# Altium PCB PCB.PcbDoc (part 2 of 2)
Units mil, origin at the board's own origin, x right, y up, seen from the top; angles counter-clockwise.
Board outline 2750 x 2500 mil, 2 copper layers (Top Layer, Bottom Layer), stack 62 mil thick; 49 components, 22 nets, 97 pads, 5 vias.
Unrouted connection lines stored in the file: 2.
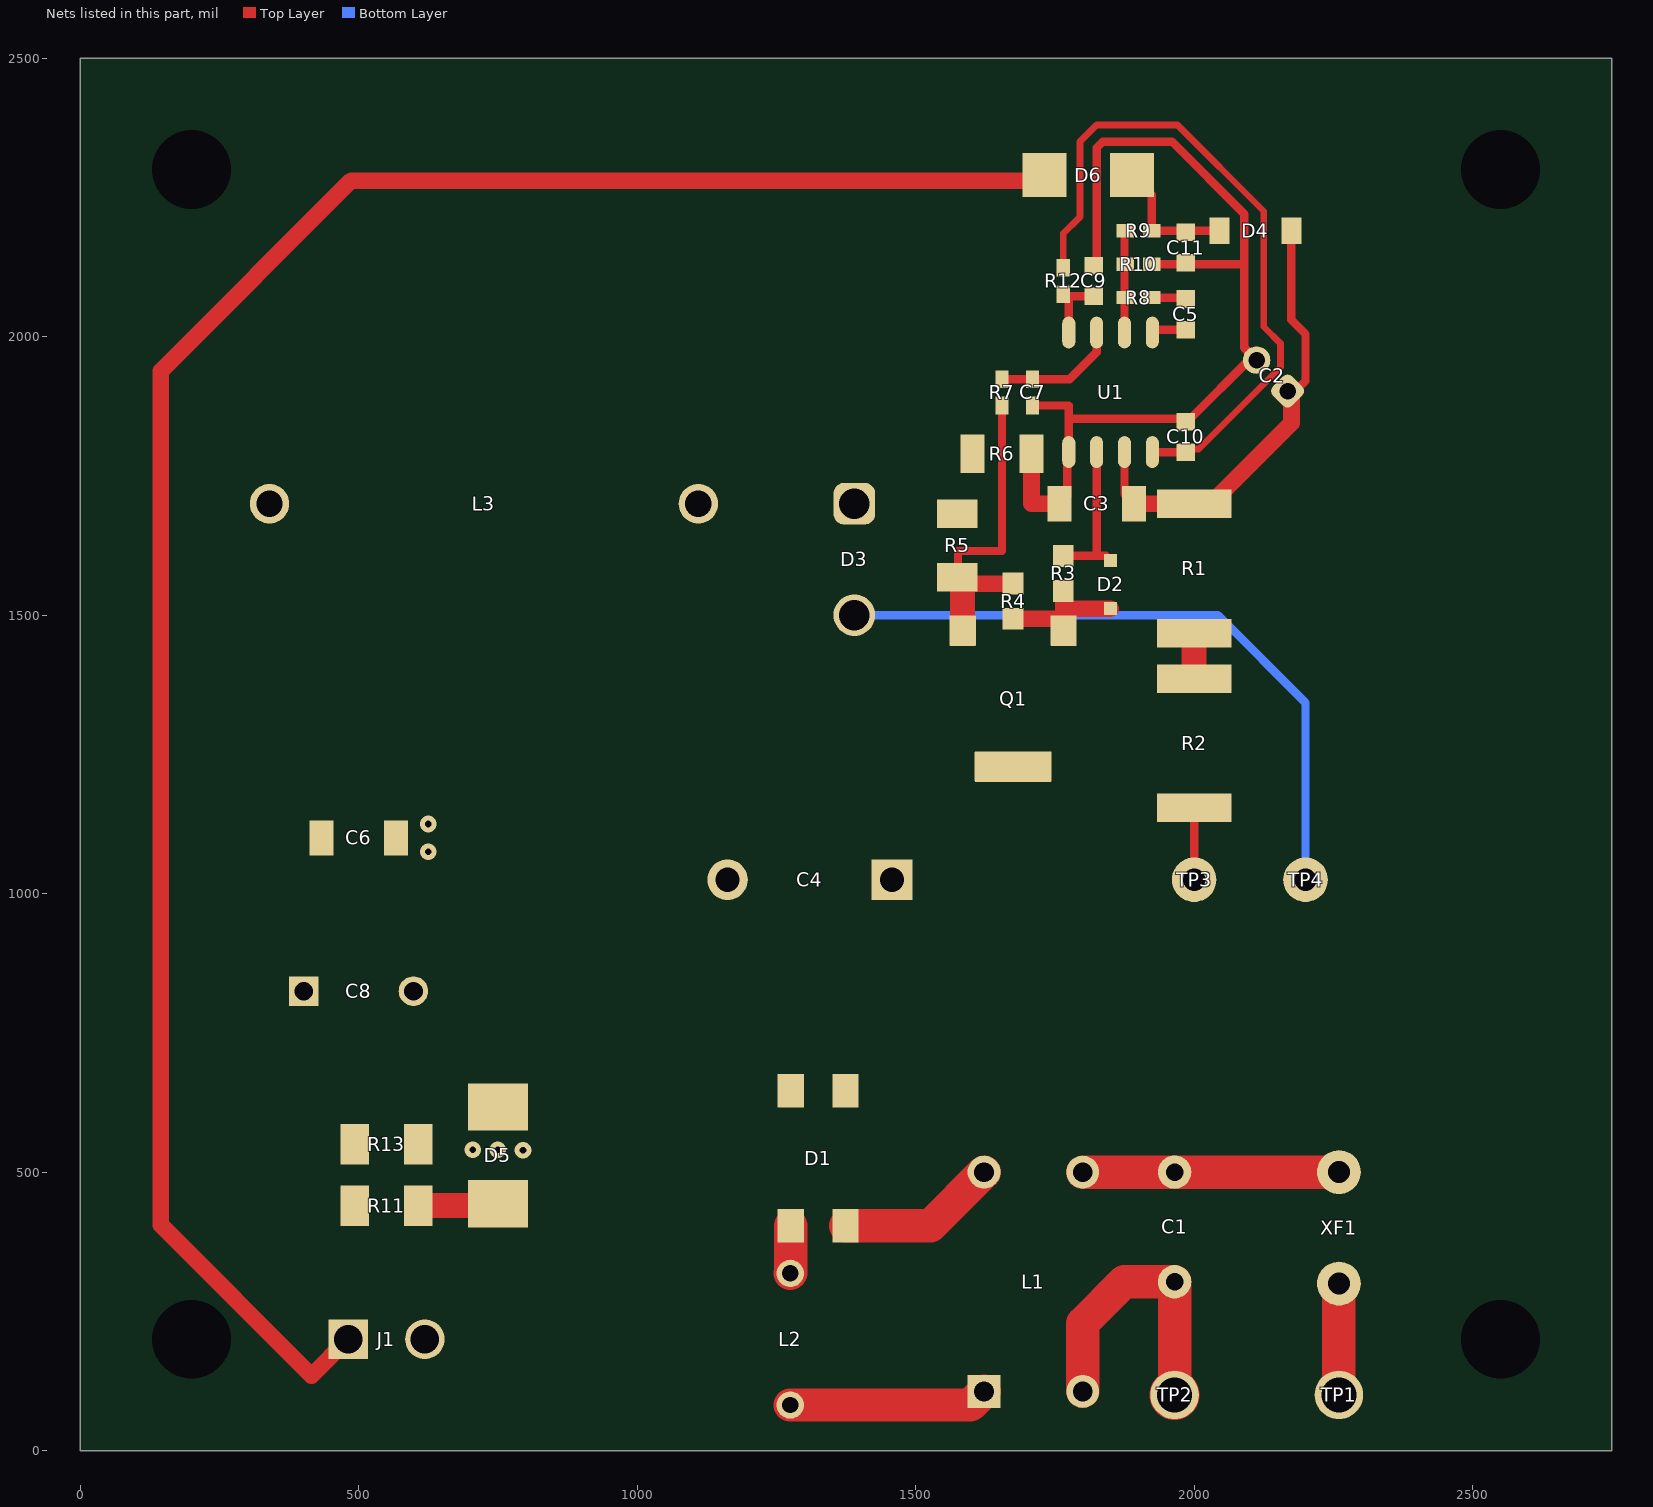
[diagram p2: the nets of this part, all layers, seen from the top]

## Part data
C1: library part CMP-0012332-3, "CAP, Film, 0.1 uF, 250 V, +/- 10%, TH", Cap_Case=4.5x9.5x7.3mm, Manufacturer=TDK, Supplier Part Number 1=495-2532-ND, Tolerance_%=10%, Value1=Unknown, Value2=250V, ValueDisplayed=0.1uF
C2: library part CMP-0064886-1, "CAP, AL, 22 uF, 25 V, +/- 20%, TH", Cap_Case=5x11mm, Manufacturer=Nichicon, Supplier Part Number 1=493-12773-1-ND, Tolerance_%=20%, Value1=Unknown, Value2=25V, ValueDisplayed=22uF
C3 C6: library part CMP-0008968-2, "CAP, CERM, 2.2 uF, 50 V, +/- 10%, X7R, 1206", Cap_Case=1206, Manufacturer=MuRata, Supplier Part Number 1=490-3367-1-ND, TempCo=X7R, Tolerance_%=10%, Value1=Unknown, Value2=50V, ValueDisplayed=2.2uF
C4: library part CMP-0010021-3, "CAP, AL, 47 uF, 250 V, +/- 20%, 0.380955 ohm, TH", AC_Derating=0.3, Manufacturer=Panasonic, Supplier Part Number 1=P13536-ND, Tolerance_%=20%, Value1="0.380955 ohm", Value2=250V, ValueDisplayed=47uF
C5 C11: library part CMP-0007415-4, "CAP, CERM, 0.22 uF, 25 V, +/- 10%, X7R, 0603", Cap_Case=0603, Manufacturer=MuRata, Supplier Part Number 1=490-3290-1-ND, TempCo=X7R, Tolerance_%=10%, Value1=Unknown, Value2=25V, ValueDisplayed=0.22uF
C7: library part CMP-0006410-2, "CAP, CERM, 100 pF, 50 V, +/- 5%, C0G/NP0, 0402", Cap_Case=0402, Manufacturer=MuRata, Supplier Part Number 1=81-GRM1555C1H101JA1D, TempCo=C0G/NP0, Tolerance_%=5%, Value1=Unknown, Value2=50V, ValueDisplayed=100pF
C8: library part CMP-0010541-2, "CAP, AL, 470 uF, 35 V, +/- 20%, 0.03 ohm, TH", Cap_Case=10x16mm, Manufacturer=Nichicon, Supplier Part Number 1=493-6882-ND, Tolerance_%=20%, Value1="0.03 ohm", Value2=35V, ValueDisplayed=470uF
C9: library part CMP-0007402-5, "CAP, CERM, 1000 pF, 25 V, +/- 10%, X7R, 0603", Cap_Case=0603, Manufacturer=MuRata, Supplier Part Number 1=GRM188R71E102KA01D-ND, TempCo=X7R, Tolerance_%=10%, Value1=Unknown, Value2=25V, ValueDisplayed=1000pF
C10: library part CMP-0007405-5, "CAP, CERM, 1 uF, 25 V, +/- 10%, X7R, 0603", Cap_Case=0603, Manufacturer=MuRata, Supplier Part Number 1=490-5307-1-ND, TempCo=X7R, Tolerance_%=10%, Value1=Unknown, Value2=25V, ValueDisplayed=1uF
D1: library part CMP-0029217-3, "Diode, Switching-Bridge, 400 V, 0.8 A, MiniDIP", Manufacturer="Diodes Inc.", Value1=0.8A, Value2=1V
D2: library part CMP-0029045-2, "Diode, Switching, 100 V, 0.2 A, SOD-323", Manufacturer="Micro Commercial Components", Value1=0.2A, Value2=1V
D3: library part CMP-0028844-2, "Diode, Schottky, 300 V, 30 A, TH", Manufacturer="Power Integrations", Value1=30A, Value2=1.95V
D4: library part CMP-0029001-2, "Diode, Ultrafast, 100 V, 0.15 A, SOD-123", Manufacturer="Diodes Inc.", Value1=0.15A, Value2=1.25V
D5: library part CMP-0005557-4, "Diode, TVS, Uni, 24 V, 38.9 Vc, SMB", Manufacturer="Diodes Inc.", Value1=600W
D6: library part CMP-0067545-2, "Diode, Superfast Rectifier, 600 V, 1 A, SMA", Manufacturer="SMC Diode Solutions", Value1=1A, Value2=1.7V
H1 H2 H3 H4: library part CMP-0003652-1, Manufacturer=Keystone, Supplier Part Number 1=36-4820-ND
J1: library part CMP-0054825-2, "Terminal Block, 3.5mm, 2x1, Tin, TH", Color=Green, Current_A=10A, Manufacturer="Wurth Elektronik", Supplier Part Number 1=732-2747-ND, Voltage_V=300V
L1: library part CMP-0084275-1, "Coupled inductor, 5 mH, 0.22 ohm, TH", Manufacturer="Wurth Elektronik", ValueDisplayed=5mH
L2: library part CMP-0064732-2, "Inductor, Toroid, Powdered Iron, 140 uH, 1 A, 0.11 ohm, TH", Manufacturer="Wurth Elektronik", Value1="0.11 ohm", Value2=1A, ValueDisplayed=140uH
L3: library part CMP-0074883-1, "Inductor, Wirewound, Ferrite, 470 µH, 4 A, 0.187 ohm, TH", Manufacturer=Bourns, Supplier Part Number 1=M8368-ND, Value1="0.187 ohm", Value2=4A, ValueDisplayed=470µH
LOGO1: library part CMP-0074835-1, "IEC 61010-1 High Voltage Warning"
Logo2: library part CMP-0074769-1
Logo3: library part CMP-0074847-1, "FCC_disclaimer"
Logo4: library part CMP-0074836-1, "IEC 61010-1 Caution Warning"
Q1: library part CMP-0087676-1, "MOSFET N-CHANNEL 600V 9A SOT223", Manufacturer=Infineon
R1 R2: library part CMP-0015941-3, "RES, 330 k, 5%, 1 W, AEC-Q200 Grade 0, 2512", Manufacturer=Vishay-Dale, PartNumber=CRCW2512330KJNEG, Power_W=1W, Supplier Part Number 1=541-330KXCT-ND, TempCo="200 ppm/C", Tolerance_%=5%, Value_Code=330k
R3: library part CMP-0022003-4, "RES, 10.0, 1%, 0.1 W, AEC-Q200 Grade 0, 0603", Manufacturer=Vishay-Dale, Power_W=100mW, Supplier Part Number 1=541-10.0HCT-ND, TempCo="100 ppm/C", Tolerance_%=1%, Value2=0.1W, Value_Code=10R0, ValueDisplayed=10.0
R4: library part CMP-0021990-4, "RES, 100 k, 1%, 0.1 W, AEC-Q200 Grade 0, 0603", Manufacturer=Vishay-Dale, Power_W=100mW, Supplier Part Number 1=541-100KHCT-ND, TempCo="100 ppm/C", Tolerance_%=1%, Value2=0.1W, Value_Code=100k
R5: library part CMP-0017274-2, "RES, 0.62, 1%, 0.5 W, 1206", Manufacturer="Stackpole Electronics Inc", Power_W=500mW, Supplier Part Number 1=CSR1206FTR620-ND, TempCo="100 ppm/C", Tolerance_%=1%, Value2=0.5W, Value_Code=R620, ValueDisplayed=0.62
R6: library part CMP-0018573-3, "RES, 0, 5%, 0.25 W, AEC-Q200 Grade 0, 1206", Manufacturer=Vishay-Dale, Power_W=250mW, Supplier Part Number 1=541-0.0ECT-ND, TempCo="200 ppm/C", Tolerance_%=5%, Value2=0.25W, Value_Code=0000, ValueDisplayed=0
R7: library part CMP-0026436-2, "RES, 511, 1%, 0.063 W, AEC-Q200 Grade 0, 0402", Manufacturer=Vishay-Dale, Power_W=63mW, Supplier Part Number 1=541-511LCT-ND, TempCo="100 ppm/C", Tolerance_%=1%, Value2=0.063W, Value_Code=511R, ValueDisplayed=511
R8: library part CMP-0026403-2, "RES, 49.9 k, 1%, 0.063 W, AEC-Q200 Grade 0, 0402", Manufacturer=Vishay-Dale, Power_W=63mW, Supplier Part Number 1=541-49.9KLCT-ND, TempCo="100 ppm/C", Tolerance_%=1%, Value2=0.063W, Value_Code=49k9, ValueDisplayed=49.9k
R9: library part CMP-0026178-2, "RES, 22.1 k, 1%, 0.063 W, AEC-Q200 Grade 0, 0402", Manufacturer=Vishay-Dale, Power_W=63mW, Supplier Part Number 1=541-22.1KLCT-ND, TempCo="100 ppm/C", Tolerance_%=1%, Value2=0.063W, Value_Code=22k1, ValueDisplayed=22.1k
R10: library part CMP-0026237-2, "RES, 2.49 k, 1%, 0.063 W, AEC-Q200 Grade 0, 0402", Manufacturer=Vishay-Dale, Power_W=63mW, Supplier Part Number 1=541-2.49KLCT-ND, TempCo="100 ppm/C", Tolerance_%=1%, Value2=0.063W, Value_Code=2k49, ValueDisplayed=2.49k
R11: library part CMP-0016583-3, "RES, 10.0, 1%, 0.25 W, AEC-Q200 Grade 0, 1206", Manufacturer=Vishay-Dale, PartNumber=CRCW120610R0FKEA, Power_W=250mW, Supplier Part Number 1=541-10.0FCT-ND, TempCo="100 ppm/C", Tolerance_%=1%, Value2=0.25W, Value_Code=10R0, ValueDisplayed=10.0
R12: library part CMP-0026371-2, "RES, 41.2 k, 1%, 0.063 W, AEC-Q200 Grade 0, 0402", Manufacturer=Vishay-Dale, Power_W=63mW, Supplier Part Number 1=541-41.2KLCT-ND, TempCo="100 ppm/C", Tolerance_%=1%, Value2=0.063W, Value_Code=41k2, ValueDisplayed=41.2k
R13: library part CMP-0018703-3, "RES, 5.1 k, 5%, 0.25 W, AEC-Q200 Grade 0, 1206", Manufacturer=Vishay-Dale, PartNumber=CRCW12065K10JNEA, Power_W=250mW, Supplier Part Number 1=541-5.1KECT-ND, TempCo="200 ppm/C", Tolerance_%=5%, Value2=0.25W, Value_Code=5k10, ValueDisplayed=5.1k
TP1: library part CMP-0055157-1, "Test Point, Multipurpose, Brown, TH", Color=Brown, Manufacturer=Keystone, Supplier Part Number 1=36-5125-ND
TP2: library part CMP-0055156-1, "Test Point, Multipurpose, Blue, TH", Color=Blue, Manufacturer=Keystone, Supplier Part Number 1=36-5127-ND
TP3: library part CMP-0055137-1, "Test Point, Miniature, Red, TH", Color=Red, Manufacturer=Keystone, Supplier Part Number 1=36-5000-ND
TP4: library part CMP-0055138-1, "Test Point, Miniature, Black, TH", Color=Black, Manufacturer=Keystone, Supplier Part Number 1=36-5001-ND
U1: library part CMP-0031461-1, "High-Performance Current-Mode PWM Controllers with Current control, 100% Duty Cycle, -40 to 85 degC, 8-pin SOIC (D),Green (RoHS & no Sb/Br)", Frequency(Max)(kHz)=500, Manufacturer="Texas Instruments", Rating=Catalog
XF1: library part CMP-0003627-1, "Fuse Holder, TR5, TH", Manufacturer=Littelfuse, Supplier Part Number 1=WK6235-ND

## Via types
v1: diameter 30, hole 12, Top Layer to Bottom Layer, 5 vias

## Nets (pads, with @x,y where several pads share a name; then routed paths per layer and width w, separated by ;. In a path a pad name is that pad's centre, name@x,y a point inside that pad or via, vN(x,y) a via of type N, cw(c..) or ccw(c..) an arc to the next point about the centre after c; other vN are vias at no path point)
24V: C6.1 C8.1 D6.2 J1.1 L3.2 R11.2 R13.2 | length 3740.6
  Top Layer w30: J1.1@481.1,200 415.55,134.45 145,405 145,1938.42 486.58,2280 1721.26,2280 D6.2@1731.26,2290
CS: Q1.3 R4.2 R5.1 R7.1 | length 578.2
  Top Layer w15: R5.1@1584.45,1558.46 1575.99,1566.91 1575.99,1615 1655,1615 R7.1@1655,1876.37
  Top Layer w30: R5.1@1584.45,1558.46 1586.41,1556.49 R4.2@1675,1556.49
  Top Layer w45: Q1.3@1584.45,1472.04 R5.1@1584.45,1558.46
GND: C4.2 C6.2 C8.2 D1.2 D3.3 D5.2 J1.2 R13.1 TP4.1 | length 1207.9
  Bottom Layer w15: D3.3@1375,1500 2042.7,1500 2200,1342.7 TP4.1@2200,1025
  other v1: 795,539.37 705,540 750,540 625,1075 625,1125
NetC1_1: C1.1 D1.4 L1.3 L1.4 XF1.2 | length 748.4
  Top Layer w60: D1.4@1374.21,403.93 1526.76,403.93 L1.4@1622.83,500 ; L1.3@1800,500 C1.1@1965,500 XF1.2@2260,500
NetC1_2: C1.2 L1.1 L1.2 L2.1 TP2.1 | length 879.4
  Top Layer w60: L2.1@1275,81.88 1598.42,81.88 L1.1@1622.83,106.3 ; L1.2@1800,106.3 1800,228.82 1874.33,303.15 C1.2@1965,303.15 TP2.1@1965,99.99
NetC2_2: C2.2 C3.2 C7.1 C9.2 C10.2 C11.2 R6.2 R10.1 U1.5 | length 1731.8
  Top Layer w15: C7.1@1710,1876.37 1775,1876.37 1775,1852.56 ; C3.2@1758.07,1700 1772.28,1714.21 1772.28,1790 U1.5@1775,1792.71 1775,1852.56 ; C9.2@1820,2127.56 1825,2132.56 1825,2338.89 1836.11,2350 1960,2350 2090,2220 2090,2130 ; R10.1@1923.62,2130 2090,2130 ; C10.2@1985,1847.56 1987.96,1847.56 2105.2,1964.8 2090,1980 2090,2130 ; C10.2@1985,1852.56 1775,1852.56
  Top Layer w30: R6.2@1708.15,1790 1708.15,1700 C3.2@1758.07,1700
NetC4_1: C4.1 D1.1 Q1.2 R2.1 TP3.1 | length 128.9
  Top Layer w15: TP3.1@2000,1025 R2.1@2000,1153.86
NetC5_1: C5.1 U1.1 | length 62.1
  Top Layer w15: U1.1@1925,2007.28 1930.15,2012.44 C5.1@1985,2012.44
NetC5_2: C5.2 R8.1 | length 62.4
  Top Layer w15: R8.1@1923.62,2070 1982.56,2070 C5.2@1985,2067.56
NetC7_2: C7.2 R7.2 U1.3 | length 225.4
  Top Layer w15: R7.2@1655,1923.62 C7.2@1710,1923.62 1776.72,1923.62 1825,1971.9 U1.3@1825,2007.28
NetC9_1: C9.1 R12.1 U1.4 | length 124.3
  Top Layer w15: R12.1@1765,2076.37 R12.1@1768.93,2072.44 ; U1.4@1775,2007.28 1775,2066.37 R12.1@1768.93,2072.44 ; C9.1@1820,2072.44 R12.1@1768.93,2072.44
NetC10_1: C10.1 R12.2 U1.8 | length 1231.2
  Top Layer w12: R12.2@1765,2123.62 1765,2185 1795,2215 1795,2350 1825,2380 1970,2380 2125,2225 2125,2017.82 2155,1987.82 2155,1945 2008.34,1798.35 C10.1@1990.91,1798.35
  Top Layer w15: U1.8@1925,1792.71 1984.73,1792.71 C10.1@1985,1792.44 C10.1@1990.91,1798.35
NetC11_1: C11.1 D4.2 D6.1 R9.2 | length 236.4
  Top Layer w15: D6.1@1888.74,2290 1923.62,2255.11 R9.2@1923.62,2190 D4.2@2045.53,2190
NetD1_3: D1.3 L2.2 | length 86.2
  Top Layer w60: L2.2@1275,318.1 1275.79,318.89 D1.3@1275.79,403.93
NetD2_1: D2.1 R3.2 U1.6 | length 274.6
  Top Layer w15: R3.2@1765,1606.49 1825,1606.49 ; U1.6@1825,1792.71 1825,1606.49 ; D2.1@1850,1598.3 1841.81,1606.49 1825,1606.49
NetD2_2: D2.2 Q1.1 R3.1 R4.1 | length 224.3
  Top Layer w30: R4.1@1675,1493.5 1763.5,1493.5 1765,1495 R3.1@1765,1543.5 ; 1765.55,1510 1767.24,1511.69 D2.2@1850,1511.69
NetD3_1: D3.1 L3.1 R5.2 R6.1
NetD5_1: D5.1 R11.1 | length 144.2
  Top Layer w45: R11.1@607.09,440 747.01,440 D5.1@750,442.99
NetR1_1: R1.1 R2.2 | length 81.6
  Top Layer w45: R2.2@2000,1386.14 R1.1@2000,1467.72
NetR8_2: R8.2 R9.1 R10.2 U1.2 | length 183.3
  Top Layer w15: U1.2@1875,2007.28 1875,2188.62 R9.1@1876.38,2190
NetTP1_1: TP1.1 XF1.1 | length 200
  Top Layer w60: TP1.1@2260,100 XF1.1@2260,300
VCC: C2.1 C3.1 D4.1 R1.2 U1.7 | length 808.8
  Top Layer w15: U1.7@1875,1792.71 1875,1716.93 C3.1@1891.93,1700 ; D4.1@2174.47,2190 2174.47,2030 2200,2004.47 2200,1920.4 C2.1@2174.8,1895.2
  Top Layer w30: C3.1@1891.93,1700 R1.2@2000,1700 2030,1700 2174.8,1844.8 C2.1@2174.8,1895.2
pads on no net: H1.0 H1.MH H2.0 H2.MH H3.0 H3.MH H4.0 H4.MH

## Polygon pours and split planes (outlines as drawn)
NetC2_2 on Top Layer "Top Layer-No Net 6" (solid, remove dead copper, pour order 10): 1745,1665 1745,2300 1825,2380 1975,2380 2150,2205 2150,1940 1875,1665
NetD3_1 on Top Layer "Top Layer-No Net 6" (solid, remove dead copper, pour order 8): 1625,1830 1625,1645 1115,1645 1085,1675 1085,1725 1190,1830
no net on Top Layer "Top Layer-No Net 6" (solid, remove dead copper, pour order 6): 1625,1828.39
GND on Top Layer "Top Layer-No Net 6" (solid, remove dead copper, pour order 4): 1300,615 1300,1050 1510,1260 1510,1440 1360,1590 500,1590 500,785 550,735 550,160 735,160 1190,615
NetC4_1 on Top Layer "Top Layer-No Net 6" (solid, remove dead copper, pour order 2): 1350,615 1350,1025 1600,1275 2070,1275 2070,1125 1910,1125 1400,615
24V on Top Layer "Top Layer-No Net 6" (solid, remove dead copper, pour order 0): 550,160 550,735 500,785 500,1590 365,1725 315,1725 180,1590 180,420 440,160
GND on Bottom Layer "Top Layer-No Net 6" (solid, remove dead copper, pour order 12): 0,0 0,2500 2750,2500 2750,1125 1910,1125 1400,615 1190,615 745,170 745,0

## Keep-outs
Keep-Out Layer:
  text ".Layer_Name" at 577,-858.49 h60

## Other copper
Top Layer:
  pour cut-out: 1925,1958.46 1840.63,1958.46 1840.63,2252.51
  pour cut-out: 1925,1841.53 1825,1841.53 1792.73,1809.27 1792.73,1656.84
  text ".Layer_Name" at 577,-858.49 h60
Bottom Layer:
  text ".Layer_Name" at 577,-858.49 h60

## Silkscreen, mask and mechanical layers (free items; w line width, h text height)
Top Overlay:
  text "'.PRJ_Number'.PCB_Rev" at 2000,800 h120
  text ".Layer_Name" at 577,-858.49 h60
Bottom Overlay:
  text ".Layer_Name" at 577,-858.49 h60
Top Paste:
  text ".Layer_Name" at 577,-858.49 h60
Bottom Paste:
  text ".Layer_Name" at 577,-858.49 h60
Top Solder:
  text ".Layer_Name" at 577,-858.49 h60
  text ".Layer_Name" at 577,-858.49 h60
Bottom Solder:
  text ".Layer_Name" at 577,-858.49 h60
Drill Guide:
  text ".Layer_Name" at 577,-858.49 h60
M1 Board Outline:
  the board outline again, w10
  text ".Layer_Name" at 577,-858.49 h60
M2 Board Dimensions:
  rectangle: 0,-275 125,-150
  rectangle: 125,-400 500,-275
  lines w7: 0,-275 1000,-275 ; 125,-400 125,-150 ; 250,-400 250,-150 ; 500,-400 500,-150 ; 750,-400 750,-150 ; 0,-400 1000,-400 1000,-150 0,-150 0,-400
  text ".Layer_Name" at 577,-858.49 h60
M3 3D STEP Top:
  text ".Layer_Name" at 577,-858.49 h60
M4 3D STEP Bottom:
  text ".Layer_Name" at 577,-858.49 h60
M5 Assembly Top:
  lines w10: -292,-930.17 6308,-930.17 ; -292,-726.83 6310,-726.83 ; -292,-523.5 -292,-1133.5 3713,-1133.5 6310,-1133.5 6310,-523.5 -291.5,-523.5 -291.5,-1133.5 1284,-1133.5 ; 2173,-1133.5 2173,-523.5 ; 3440,-726.83 3440,-523.5 ; 4280,-726.83 4280,-523.5 ; 4902,-1140 4902,-937.17
  text "COMPONENTS MARKED 'DNP' SHOULD NOT BE POPULATED." at 1153.5,-318.5 h60
  text "ASSEMBLY VARIANT:" at 1153,-434 h60
  text ".VariantName" at 2189,-434 h60
  text "PCB VIEWED FROM TOP SIDE" at -228.5,-655.67 h60
  text "BOARD #:" at 2248,-655.67 h60
  text ".PRJ_Number" at 2793.5,-655.67 h60
  text "REV:" at 3638,-655.67 h60
  text ".PCB_Rev" at 3929.5,-655.67 h60
  text "SVN REV:" at 4476,-655.67 h60
  text ".VersionControl_RevNumber" at 4982,-655.67 h60
  text "TID #:" at 2248,-859 h60
  text ".TID" at 2793.5,-859 h60
  text "PLOT NAME =" at -228.5,-1064.34 h60
  text ".plot_File_Name" at 577,-1064.34 h60
  text "GENERATED    :" at 2250,-1064.34 h60
  text ".Print_Date" at 3119.5,-1064.34 h60
  text ".Print_Time" at 3848.5,-1064.34 h60
  text "TEXAS INSTRUMENTS" at 5113,-1064.34 h60
M6 Assembly Bottom:
  lines w10: -292.5,-727.33 6309.5,-727.33 ; -290.5,-930.67 6309.5,-930.67 ; 1115.5,-1140.5 1115.5,-937.67 ; 1737.5,-727.33 1737.5,-524 ; 2577.5,-727.33 2577.5,-524 ; 3844.5,-1134 3844.5,-524 ; 4733.5,-1134 6309,-1134 6309,-524 -292.5,-524 -292.5,-1134 2304.5,-1134 6309.5,-1134 6309.5,-524
  text "COMPONENTS MARKED 'DNP' SHOULD NOT BE POPULATED." at 6102,-318 h60
  text ".VariantName" at 5058,-434 h60
  text "ASSEMBLY VARIANT:" at 6097,-434 h60
  text ".VersionControl_RevNumber" at 1035.5,-656.17 h60
  text "SVN REV:" at 1541.5,-656.17 h60
  text ".PCB_Rev" at 2088,-656.17 h60
  text "REV:" at 2379.5,-656.17 h60
  text ".PRJ_Number" at 3224,-656.17 h60
  text "BOARD #:" at 3769.5,-656.17 h60
  text "PCB VIEWED FROM BOTTOM SIDE" at 6246,-656.17 h60
  text ".TID" at 3224,-859.5 h60
  text "TID #:" at 3769.5,-859.5 h60
  text "TEXAS INSTRUMENTS" at 904.5,-1064.84 h60
  text ".Print_Time" at 2169,-1064.84 h60
  text ".Print_Date" at 2898,-1064.84 h60
  text "GENERATED    :" at 3767.5,-1064.84 h60
  text ".plot_File_Name" at 5440.5,-1064.84 h60
  text "PLOT NAME =" at 6246,-1064.84 h60
M9 Title Sheet:
  drawing of 57 lines, arcs and shapes, not listed
  text "1" at 739.84,8036.5 h70
  text "2" at 3235.5,8036.5 h70
  text "3" at 5724.84,8036.5 h70
  text "4" at 8231.51,8036.5 h70
  text "5" at 10730.5,8036.5 h70
  text "6" at 13235.5,8036.5 h70
  text "A" at -416.5,6893.5 h70
  text "A" at 14383.5,6893.5 h70
  text "B" at -416.5,4513.5 h70
  text "B" at 14383.5,4513.5 h70
  text "C" at -416.5,2138.5 h70
  text "C" at 14383.5,2138.5 h70
  text "PROJECT TITLE:" at 11343.5,277.5 h45
  text ".PRJ_Title" at 11393.5,144.17 h70
  text "DESIGNED FOR:" at 11343.5,-23.5 h45
  text ".PRJ_Customer" at 11393.5,-163.5 h70
  text "D" at -416.5,-231.5 h70
  text "D" at 14383.5,-231.5 h70
  text "FILE NAME:" at 11343.5,-323.5 h45
  text ".PCB_File_Name_No_Path" at 11393.5,-443.5 h70
  text "Texas Instruments (TI) and/or its licensors do not warrant the accuracy or completeness of this specification" at 6374,-605.34 h45
  text "ENGINEER:" at 11343.5,-613.5 h45
  text "LAYOUT BY:" at 12848.5,-613.5 h45
  text "or any information contained therein. TI and/or its licensors do not warrant that this design will meet" at 6329.01,-718 h45
  text ".PRJ_Engineer" at 11393.5,-768.49 h70
  text ".PCB_Layout" at 12899,-768.49 h70
  text "the specifications, will be suitable for your application or fit for any particular purpose, or will operate in" at 6329.01,-830.67 h45
  text ".Layer_Name" at 577,-858.49 h60
  text "ALTIUM DESIGNER VERSION:" at 12848.5,-923.5 h45
  text "an implementation. TI and/or its licensors do not warrant that the design is production worthy. You should" at 6329.01,-943.33 h45
  text "completely validate and test your design implementation to confirm the system functionality for your application." at 6374,-1056 h45
  text ".print_Scale" at 11393.5,-1056.83 h70
  text ".Application_BuildNumber" at 12899,-1056.83 h70
  text "1" at 739.84,-1263.5 h70
  text "2" at 3235.5,-1263.5 h70
  text "3" at 5724.84,-1263.5 h70
  text "4" at 8231.51,-1263.5 h70
  text "5" at 10730.5,-1263.5 h70
  text "6" at 13235.5,-1263.5 h70
M10 Fab Notes:
  drawing of 189 lines, arcs and shapes, not listed
  text "DESIGN INFORMATION" at 12382.02,6356.17 h60
  text "MIN. TRACK WIDTH:" at 11737.46,6224.05 h60
  text "8" at 12833.7,6224.05 h60
  text "MIL" at 12988.46,6224.05 h60
  text "MIN. CLEARANCE:" at 11737.46,6099.92 h60
  text "0.2" at 12773.7,6099.93 h60
  text "mm" at 12988.46,6099.92 h60
  text "MIN. VIA PAD SIZE:" at 11737.46,5975.8 h60
  text "24" at 12803.71,5975.8 h60
  text "MIL" at 12988.46,5975.8 h60
  text "0.05mm (2MIL)" at 12432.46,5845.9 h60
  text "MINIMUM ANNULAR RING" at 11408.23,5837.67 h60
  text "EXTERNAL" at 13140.46,5837.67 h60
  text "PER" at 11608.23,5727.55 h60
  text "IPC-D-275 CLASS 2 LEVEL C" at 11828.23,5727.54 h60
  text "MIL, HOLES" at 13316.46,5627.07 h60
  text "+/-" at 12924,5618.48 h60
  text "+/-" at 13778,5618.48 h60
  text "REGISTRATION TOLERANCES:" at 11408.23,5617.42 h60
  text "METAL" at 12608,5617.42 h60
  text "5" at 13184.2,5617.42 h60
  text "3" at 14017.2,5617.42 h60
  text "MIL" at 14133.46,5617.42 h60
  text "HOLE SIZE TOLERANCE (UNLESS OTHERWISE SPECIFIED):" at 11408.23,5519.1 h60
  text "+/-" at 13778,5516.23 h60
  text "3" at 14017.2,5515.17 h60
  text "MIL" at 14133.46,5515.17 h60
  text "MATERIAL:" at 11333.46,5377.52 h60
  text "FR-4 High Tg" at 12319.9,5249 h60
  text "X" at 12175.46,5241.01 h60
  text "FR-408" at 11754.46,5236.49 h60
  text "OTHER" at 13242.46,5236.49 h60
  text "62 MIL (1.6mm) +/-10%" at 12074.56,5093.46 h60
  text "X" at 11954.46,5091.01 h60
  text "THICKNESS:" at 11408.23,5085.24 h60
  text "OTHER" at 13359.46,5085.24 h60
  text "TOLERANCE:" at 11408.23,4946.92 h60
  text "X" at 12256.46,4946.92 h60
  text "ANSI IPC-6012 TYPE 3 CLASS 2" at 12434.48,4946.92 h60
  text "OTHER +/-" at 12434.46,4802.73 h60
  text "BOW & TWIST:" at 11408.23,4657.54 h60
  text "X" at 12256.46,4657.54 h60
  text "ANSI IPC-6012 TYPE 3 CLASS 2" at 12434.48,4657.54 h60
  text "OTHER +/-" at 12434.46,4510.85 h60
  text "DRILLING:" at 11333.46,4380.23 h60
  text "NC_DRILL FILES" at 13094.46,4275.04 h60
  text "REFERENCE:" at 11408.23,4271.1 h60
  text "X" at 12065.46,4271.01 h60
  text "AS SHOWN" at 12243.46,4271.1 h60
  text "X" at 12966.46,4271.1 h60
  text "OTHER" at 13392.46,4128.85 h60
  text "PTH COPPER THICKNESS:" at 11407.91,4125.32 h60
  text "X" at 12547.14,4125.32 h60
  text "20-30 um" at 12675.14,4125.32 h60
  text "BOARD FINISH:" at 11333.46,3977.73 h60
  text "SILKSCREEN:" at 11488.68,3867.6 h60
  text "X" at 12446.46,3867.6 h60
  text "TOP" at 12563.46,3867.6 h60
  text "X" at 12956.46,3867.6 h60
  text "BOTTOM" at 13074.46,3867.6 h60
  text "SILKSCREEN COLOR:" at 11488.68,3712.41 h60
  text "X" at 12445.46,3712.41 h60
  text "WHITE" at 12563.46,3712.41 h60
  text "OTHER" at 13074.46,3712.41 h60
  text "X" at 12576.46,3568.96 h60
  text "GREEN" at 12694.46,3568.96 h60
  text "OTHER" at 13312.46,3568.96 h60
  text "SOLDER RESIST COLOR:" at 11488.68,3562.1 h60
  text "X" at 12576.46,3414.71 h60
  text "MATTE" at 12694.46,3414.71 h60
  text "SEMI-GLOSS" at 13312,3414.07 h60
  text "IMMERSION GOLD (ENIG)" at 12394.46,3241.94 h60
  text "ENEPIG" at 13732,3234.72 h60
  text "SURFACE FINISH:" at 11333.46,3233.72 h60
  text "X" at 12216.46,3233.72 h60
  text "IMM. TIN/SILVER OR EQUIV" at 11663,3096.4 h60
  text "OTHER" at 13094.46,3092.47 h60
  text "ARRAY/PANEL:" at 11333.46,2937.09 h60
  text "CUT AND TRIM PER M1 BOARD OUTLINE" at 12394.46,2928.87 h60
  text "N.C. ROUTE" at 12394.46,2792.9 h60
  text "X" at 13082.46,2792.9 h60
  text "V. SCORE" at 13260.46,2792.9 h60
  text "CERTIFICATION:" at 11333.46,2663.77 h60
  text "MATERIALS AND WORKMANSHIP FOR ALL PCBS" at 12058.46,2663.77 h60
  text "TO MEET OR EXCEED THE REQUIREMENTS OF:" at 12058.46,2569.71 h60
  text "X" at 11695.97,2441.08 h60
  text "ANSI IPC-A-600F CLASS ->" at 11823.96,2441.08 h60
  text "X" at 13471.97,2441.08 h60
  text "2" at 13581.96,2441.08 h60
  text "1" at 13266.96,2439.58 h60
  text "3" at 13935.96,2439.58 h60
  text "X" at 12507.97,2293.39 h60
  text "RoHS" at 12635.96,2293.39 h60
  text "OTHER" at 13280.36,2293.39 h60
  text "PER ORDER" at 13677.42,2293.39 h60
  text "ALL BOARDS MUST MEET OR EXCEED UL94-V0 REQUIREMENTS." at 11361,2139.57 h60
  text "PCB MUST BEAR THE UL94V-0 UL REGISTERED MATERIAL ID NUMBER" at 11361,2023.5 h60
  text "ADDITIONAL REQUIREMENTS:" at 11333.46,1854.08 h60
  text "MICROSECTION:" at 11408.23,1746.95 h60
  text "YES" at 12313.96,1746.95 h60
  text "REQUIRED" at 13175.46,1602.62 h60
  text "BARE BOARD ELEC. TEST:" at 11408.23,1599.76 h60
  text "NONE" at 12713.96,1599.76 h60
  text "X" at 13057.46,1599.76 h60
  text "PER ORDER" at 13767.46,1599.76 h60
  text "XX MIL VIAS REQUIRE NON-CONDUCTIVE FILL AND PLANARIZE" at 11576.38,1394.82 h59
  text "XX MIL VIAS REQUIRE CONDUCTIVE FILL AND PLANARIZE" at 11584.38,1290.84 h60
  text "OUTER XX MIL TRACES REQUIRE 50 OHM SINGLE-ENDED IMPEDANCE" at 11583.39,1127.46 h58
  text "LAYER 2 & 3 (INNER LAYERS) XX MIL WIDE, XX MIL SPACE / TRACES REQUIRE 100 OHM DIFFERENTIAL IMPEDANCE" at 11575.39,891.74 h60
  text ".Layer_Name" at 577,-858.49 h60
M11 Gerber Information:
  lines w10: -292,-930.17 6308,-930.17 ; -292,-726.83 6310,-726.83 ; -292,-523.5 -292,-1133.5 3713,-1133.5 6310,-1133.5 6310,-523.5 -291.5,-523.5 -291.5,-1133.5 1284,-1133.5 ; 2173,-1133.5 2173,-523.5 ; 3440,-726.83 3440,-523.5 ; 4280,-726.83 4280,-523.5 ; 4902,-1140 4902,-937.17
  text "ALL ARTWORK VIEWED FROM TOP SIDE" at -228.5,-655.67 h60
  text "BOARD #:" at 2248,-655.67 h60
  text ".PRJ_Number" at 2793.5,-655.67 h60
  text "REV:" at 3638,-655.67 h60
  text ".PCB_Rev" at 3929.5,-655.67 h60
  text "SVN REV:" at 4476,-655.67 h60
  text ".VersionControl_RevNumber" at 4982,-655.67 h60
  text "LAYER NAME =" at -228.5,-858.49 h60
  text "TID #:" at 2248,-859 h60
  text ".TID" at 2793.5,-859 h60
  text "PLOT NAME =" at -228.5,-1064.34 h60
  text ".plot_File_Name" at 577,-1064.34 h60
  text "GENERATED    :" at 2250,-1064.34 h60
  text ".Print_Date" at 3119.5,-1064.34 h60
  text ".Print_Time" at 3848.5,-1064.34 h60
  text "TEXAS INSTRUMENTS" at 5113,-1064.34 h60
M12 Stackup:
  drawing of 191 lines, arcs and shapes, not listed
  text "Layer" at 9797.84,7672.5 h60
  text "Name" at 10207.76,7672.5 h60
  text "Material" at 11137.5,7672.5 h60
  text "Thickness" at 11997.27,7672.5 h60
  text "Constant" at 12647.1,7672.5 h60
  text "Board Layer Stack" at 13216.96,7672.5 h60
  text "1" at 9797.84,7552.5 h60
  text "Top Overlay" at 10207.76,7552.5 h60
  text "2" at 9797.84,7432.5 h60
  text "Top Solder" at 10207.76,7432.5 h60
  text "Solder Resist" at 11137.5,7432.5 h60
  text "0.40mil" at 11997.27,7432.5 h60
  text "3.5" at 12647.1,7432.5 h60
  text "3" at 9797.84,7312.5 h60
  text "Top Layer" at 10207.76,7312.5 h60
  text "Copper" at 11137.5,7312.5 h60
  text "1.40mil" at 11997.27,7312.5 h60
  text "4" at 9797.84,7192.5 h60
  text "Dielectric1" at 10207.76,7192.5 h60
  text "FR-4" at 11137.5,7192.5 h60
  text "59.20mil" at 11997.27,7192.5 h60
  text "4.8" at 12647.1,7192.5 h60
  text "5" at 9797.84,7072.5 h60
  text "Bottom Layer" at 10207.76,7072.5 h60
  text "Copper" at 11137.5,7072.5 h60
  text "1.40mil" at 11997.27,7072.5 h60
  text "6" at 9797.84,6952.5 h60
  text "Bottom Solder" at 10207.76,6952.5 h60
  text "Solder Resist" at 11137.5,6952.5 h60
  text "0.40mil" at 11997.27,6952.5 h60
  text "3.5" at 12647.1,6952.5 h60
  text "7" at 9797.84,6832.5 h60
  text "Bottom Overlay" at 10207.76,6832.5 h60
  text ".Layer_Name" at 577,-858.49 h60
M13 Component Bodies Top:
  text ".Layer_Name" at 577,-858.49 h60
M14 Component Bodies Bottom:
  text ".Layer_Name" at 577,-858.49 h60
M15 Courtyards Top:
  text ".Layer_Name" at 577,-858.49 h60
M16 Courtyards Bottom:
  text ".Layer_Name" at 577,-858.49 h60
Drill Drawing:
  drawing of 151 lines, arcs and shapes, not listed
  text "Symbol" at 5360.59,3404.98 h72
  text "Quantity" at 5661.16,3404.98 h72
  text "Finished Hole Size" at 5993.16,3404.98 h72
  text "Plated" at 6629.72,3404.98 h72
  text "Hole Type" at 6888.86,3404.98 h72
  text "Drill Layer Pair" at 7264.02,3404.98 h72
  text "Hole Tolerance" at 7988.35,3404.98 h72
  text "4" at 5661.16,3280.66 h60
  text "141.73mil (3.600mm)" at 5993.16,3280.66 h60
  text "NPTH" at 6629.72,3280.66 h60
  text "Round" at 6888.86,3280.66 h60
  text "Top Layer - Bottom Layer" at 7264.02,3280.66 h60
  text "5" at 5661.16,3156.34 h60
  text "12.00mil (0.305mm)" at 5993.16,3156.34 h60
  text "PTH" at 6629.72,3156.34 h60
  text "Round" at 6888.86,3156.34 h60
  text "Top Layer - Bottom Layer" at 7264.02,3156.34 h60
  text "4" at 5661.16,3032.02 h60
  text "29.53mil (0.750mm)" at 5993.16,3032.02 h60
  text "PTH" at 6629.72,3032.02 h60
  text "Round" at 6888.86,3032.02 h60
  text "Top Layer - Bottom Layer" at 7264.02,3032.02 h60
  text "2" at 5661.16,2907.7 h60
  text "31.00mil (0.787mm)" at 5993.16,2907.7 h60
  text "PTH" at 6629.72,2907.7 h60
  text "Round" at 6888.86,2907.7 h60
  text "Top Layer - Bottom Layer" at 7264.02,2907.7 h60
  text "2" at 5661.16,2783.38 h60
  text "33.47mil (0.850mm)" at 5993.16,2783.38 h60
  text "PTH" at 6629.72,2783.38 h60
  text "Round" at 6888.86,2783.38 h60
  text "Top Layer - Bottom Layer" at 7264.02,2783.38 h60
  text "4" at 5661.16,2659.06 h60
  text "35.43mil (0.900mm)" at 5993.16,2659.06 h60
  text "PTH" at 6629.72,2659.06 h60
  text "Round" at 6888.86,2659.06 h60
  text "Top Layer - Bottom Layer" at 7264.02,2659.06 h60
  text "2" at 5661.16,2534.74 h60
  text "39.37mil (1.000mm)" at 5993.16,2534.74 h60
  text "PTH" at 6629.72,2534.74 h60
  text "Round" at 6888.86,2534.74 h60
  text "Top Layer - Bottom Layer" at 7264.02,2534.74 h60
  text "2" at 5661.16,2410.42 h60
  text "40.00mil (1.016mm)" at 5993.16,2410.42 h60
  text "PTH" at 6629.72,2410.42 h60
  text "Round" at 6888.86,2410.42 h60
  text "Top Layer - Bottom Layer" at 7264.02,2410.42 h60
  text "2" at 5661.16,2286.1 h60
  text "43.31mil (1.100mm)" at 5993.16,2286.1 h60
  text "PTH" at 6629.72,2286.1 h60
  text "Round" at 6888.86,2286.1 h60
  text "Top Layer - Bottom Layer" at 7264.02,2286.1 h60
  text "2" at 5661.16,2161.78 h60
  text "47.24mil (1.200mm)" at 5993.16,2161.78 h60
  text "PTH" at 6629.72,2161.78 h60
  text "Round" at 6888.86,2161.78 h60
  text "Top Layer - Bottom Layer" at 7264.02,2161.78 h60
  text "2" at 5661.16,2037.46 h60
  text "51.18mil (1.300mm)" at 5993.16,2037.46 h60
  text "PTH" at 6629.72,2037.46 h60
  text "Round" at 6888.86,2037.46 h60
  text "Top Layer - Bottom Layer" at 7264.02,2037.46 h60
  text "2" at 5661.16,1913.14 h60
  text "55.12mil (1.400mm)" at 5993.16,1913.14 h60
  text "PTH" at 6629.72,1913.14 h60
  text "Round" at 6888.86,1913.14 h60
  text "Top Layer - Bottom Layer" at 7264.02,1913.14 h60
  text "2" at 5661.16,1788.82 h60
  text "63.00mil (1.600mm)" at 5993.16,1788.82 h60
  text "PTH" at 6629.72,1788.82 h60
  text "Round" at 6888.86,1788.82 h60
  text "Top Layer - Bottom Layer" at 7264.02,1788.82 h60
  text "35 Total" at 5661.16,1664.5 h60
  text ".Layer_Name" at 577,-858.49 h60
M17 Embedded Cavity:
  text ".Layer_Name" at 577,-858.49 h60
M18 Embedded Assembly:
  text ".Layer_Name" at 577,-858.49 h60
M19 Embedded Keepout:
  text ".Layer_Name" at 577,-858.49 h60

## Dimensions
0,-400 to 1000,-400 on M2 Board Dimensions
0,0 to 0,2500 on M2 Board Dimensions
0,0 to 2750,0 on M2 Board Dimensions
